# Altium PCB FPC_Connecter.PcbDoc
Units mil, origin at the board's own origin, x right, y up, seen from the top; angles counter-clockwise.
Board outline 1740 x 1360 mil, 2 copper layers (Top Layer, Bottom Layer); 2 components, 33 nets, 80 pads, 28 vias.
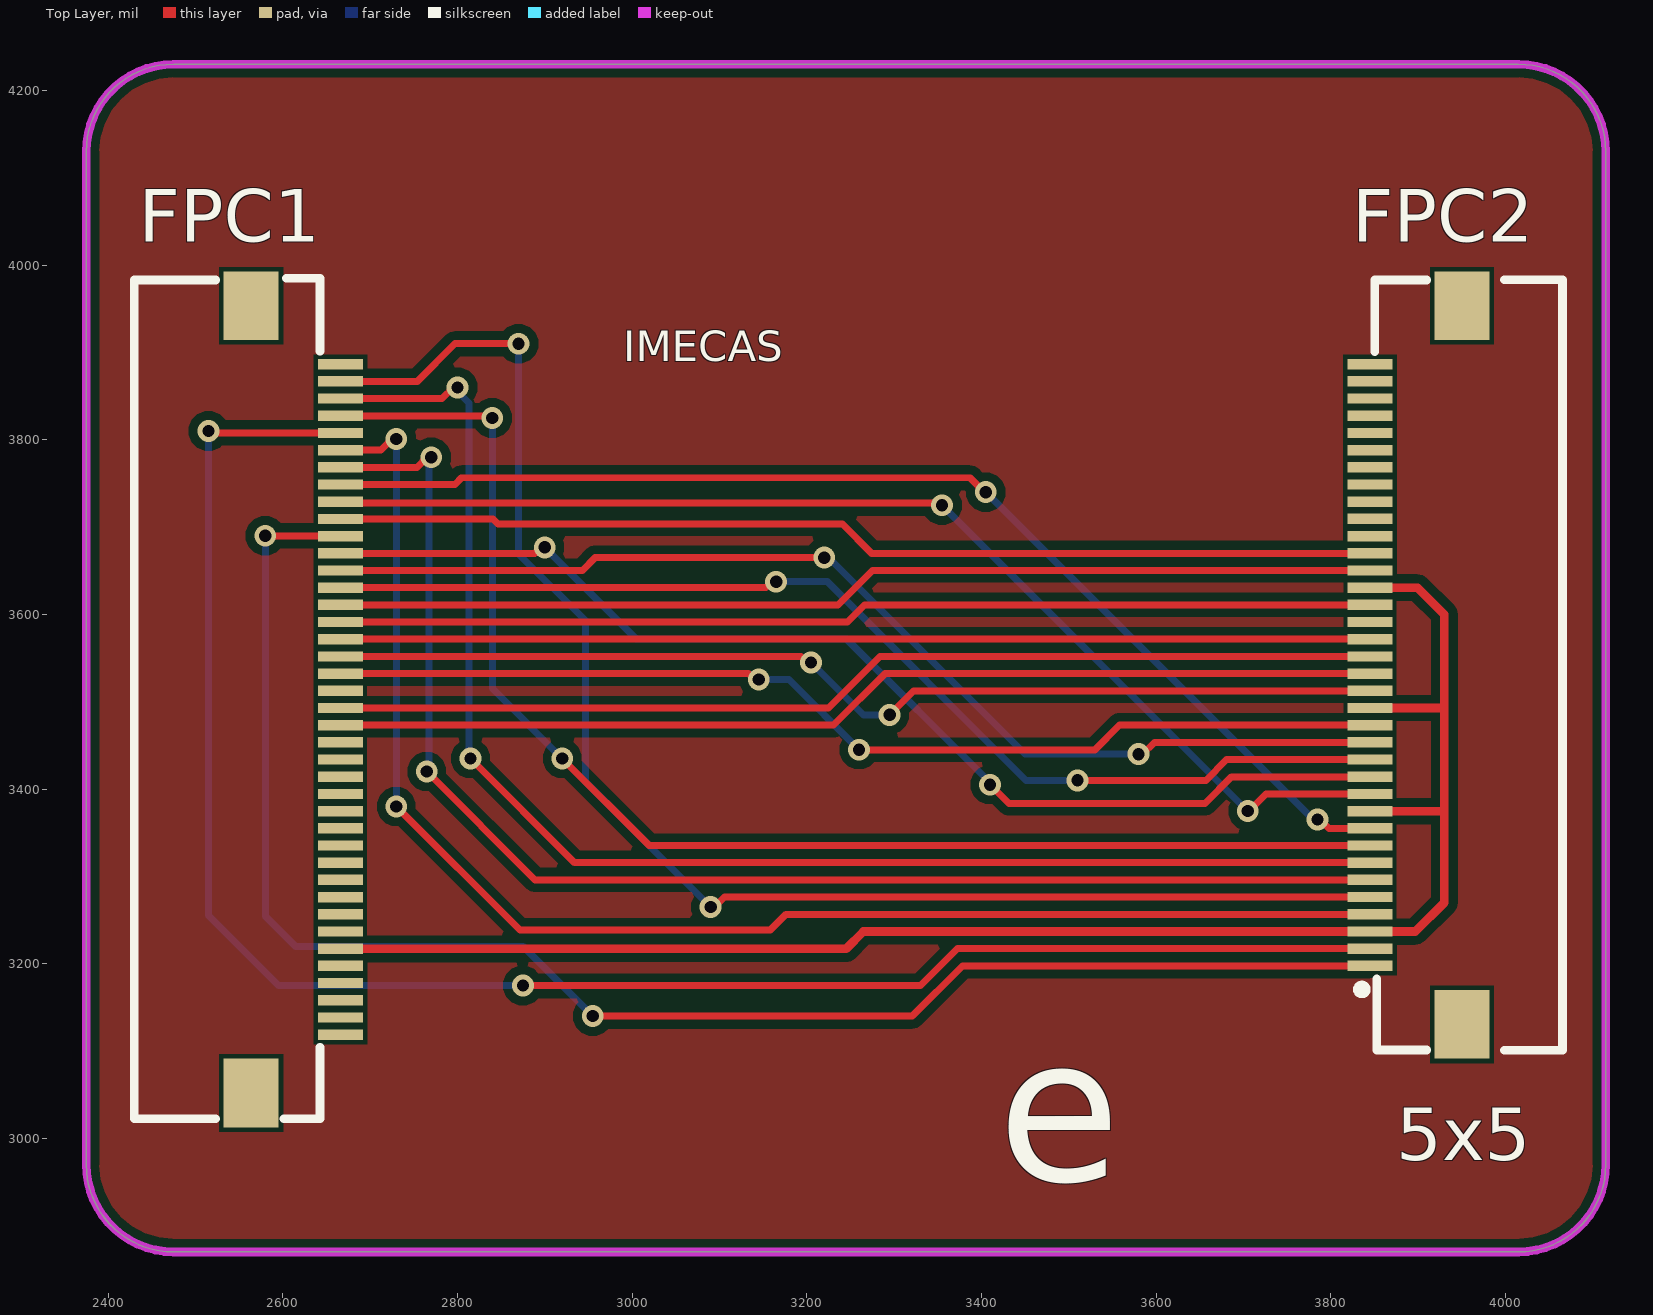
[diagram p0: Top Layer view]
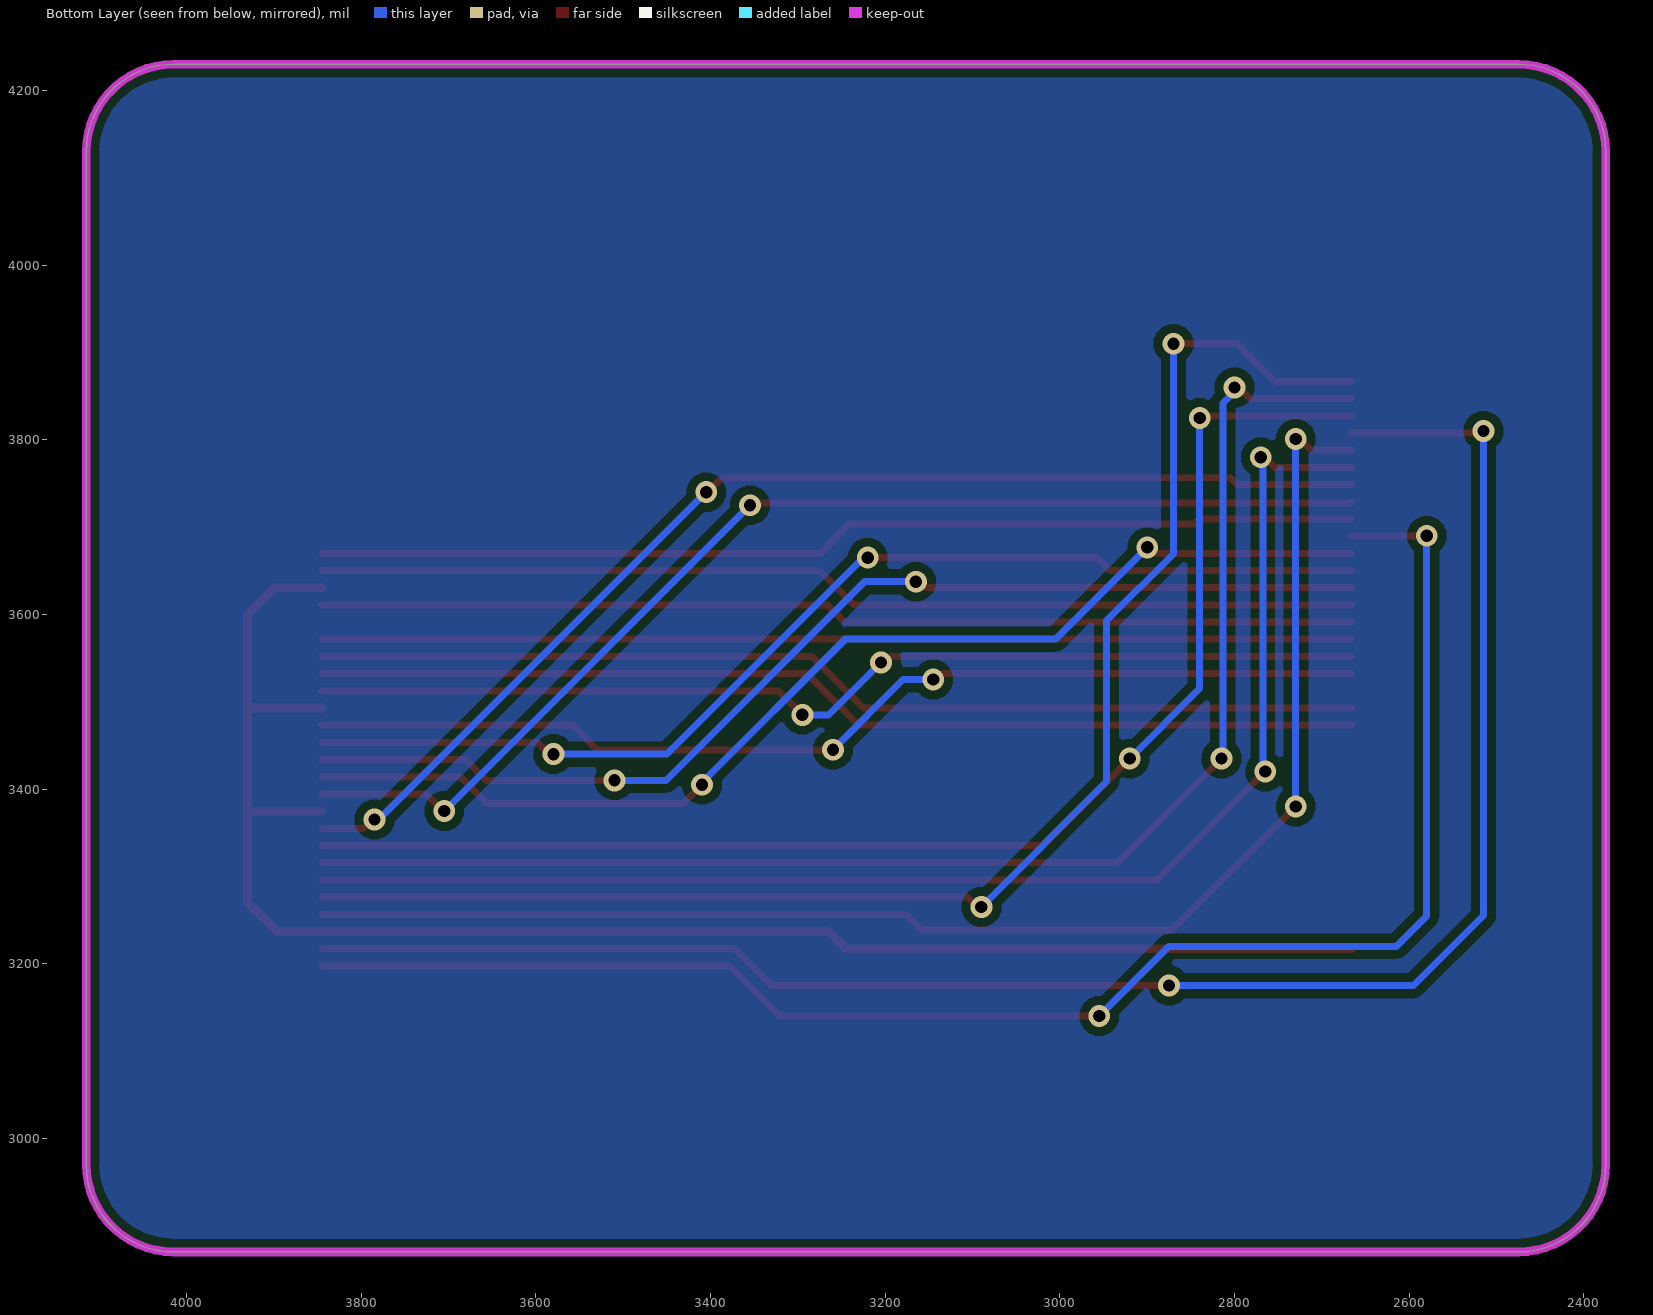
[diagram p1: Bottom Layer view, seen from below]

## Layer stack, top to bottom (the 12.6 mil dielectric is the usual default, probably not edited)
Top Solder: solder mask 0.4, Solder Resist, Dk 3.5
Top Layer: signal copper 1.4
Dielectric 1: dielectric 12.6, FR-4, Dk 4.8
Bottom Layer: signal copper 1.4
Bottom Solder: solder mask 0.4, Solder Resist, Dk 3.5

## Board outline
2375,2970 2375,4130 cw(c2475,4130) 2475,4230 4015,4230 cw(c4015,4130) 4115,4130 4115,2970 cw(c4015,2970) 4015,2870 2475,2870 cw(c2475,2970)

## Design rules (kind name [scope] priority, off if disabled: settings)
Clearance Clearance_2 [(InComponent('FPC1') OR InComponent('FPC2'))] p1: gap=5 ignorepadtopadclearanceinfootprint=FALSE
Clearance [All] p2: gap=10 ignorepadtopadclearanceinfootprint=FALSE except(0: Arc-Hole Track-Hole SMDPad-Hole THPad-Hole Via-Hole Fill-Hole Poly-Hole Region-Hole Text-Hole)
PolygonConnect [All] p1: connectstyle=Relief reliefconductorwidth=10 reliefentries=4 polygonreliefangle="90 Angle" airgapwidth=10
RoutingVias [All] p1: holewidth=14 width=25 viastyle="Through Hole" minholewidth=14 minwidth=25 maxholewidth=14 maxwidth=25
SolderMaskExpansion [All] p1: expansion=4 istentingtop=FALSE
Width [All] p1: maxlimit=10 minlimit=8 preferedwidth=8 minimp=50.000000 maximp=50.000000 favimp=50.000000
30 further rules are at their usual default settings.

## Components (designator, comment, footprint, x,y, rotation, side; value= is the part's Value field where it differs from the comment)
FPC1 "AFC01-S40FCA-00" FPC-SMD_P0.50-40P_FGS-XJ-H2.0 2615,3502.67 r90 top
FPC2 "AFC01-S36FCA-00" FPC-SMD_AFC01-S36FCA-00 3897.76,3542.05 r90 top

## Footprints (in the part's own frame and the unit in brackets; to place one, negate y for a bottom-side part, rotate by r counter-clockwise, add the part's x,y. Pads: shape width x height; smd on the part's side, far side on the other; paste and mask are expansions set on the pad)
FPC-SMD_AFC01-S36FCA-00 [mm]
  rect 0.3x1.3 smd: 1(-8.75,1.34) 2(-8.25,1.339) 3(-7.75,1.34) 4(-7.25,1.34) 5(-6.75,1.34) 6(-6.25,1.34) 7(-5.75,1.34) 8(-5.25,1.34) 9(-4.75,1.34) 10(-4.25,1.34) 11(-3.75,1.34) 12(-3.25,1.34) 13(-2.75,1.34) 14(-2.25,1.34) 15(-1.75,1.34) 16(-1.25,1.34) 17(-0.75,1.34) 18(-0.25,1.34) 19(0.25,1.34) 20(0.75,1.34) 21(1.25,1.34) 22(1.75,1.34) 23(2.25,1.34) 24(2.75,1.34) 25(3.25,1.34) 26(3.75,1.34) 27(4.25,1.34) 28(4.75,1.34) 29(5.25,1.34) 30(5.75,1.34) 31(6.25,1.34) 32(6.75,1.34) 33(7.25,1.34) 34(7.75,1.34) 35(8.25,1.34) 36(8.75,1.34)
  rect 2x1.6 smd: 37(10.45,-1.34) 38(-10.45,-1.34)
  silkscreen extent -11.21,-4.26 11.21,1.7
FPC-SMD_P0.50-40P_FGS-XJ-H2.0 [mm]
  rect 0.3x1.3 smd paste+0 mask+0.05: 1(9.75,-1.3) 2(9.25,-1.3) 3(8.75,-1.3) 4(8.25,-1.3) 5(7.75,-1.3) 6(7.25,-1.3) 7(6.75,-1.3) 8(6.25,-1.3) 9(5.75,-1.3) 10(5.25,-1.3) 11(4.75,-1.3) 12(4.25,-1.3) 13(3.75,-1.3) 14(3.25,-1.3) 15(2.75,-1.3) 16(2.25,-1.3) 17(1.75,-1.3) 18(1.25,-1.3) 19(0.75,-1.3) 20(0.25,-1.3) 21(-0.25,-1.3) 22(-0.75,-1.3) 23(-1.25,-1.3) 24(-1.75,-1.3) 25(-2.25,-1.3) 26(-2.75,-1.3) 27(-3.25,-1.3) 28(-3.75,-1.3) 29(-4.25,-1.3) 30(-4.75,-1.3) 31(-5.25,-1.3) 32(-5.75,-1.3) 33(-6.25,-1.3) 34(-6.75,-1.3) 35(-7.25,-1.3) 36(-7.75,-1.3) 37(-8.25,-1.3) 38(-8.75,-1.3) 39(-9.25,-1.3) 40(-9.75,-1.3)
  rect 2x1.6 smd: 41(-11.45,1.3) 42(11.45,1.3)
  silkscreen extent -12.2,-0.7 12.25,4.7

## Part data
FPC1: JLCPCB Part Class="Extended Part", LCSC Part Name="间距:0.5mm P数:40P 翻盖式 下接", Manufacturer=JS(钜硕电子)
FPC2: JLCPCB Part Class="Extended Part", LCSC Part Name="间距:0.5mm P数:36P 翻盖式 下接", Manufacturer=JS(钜硕电子), Operating Temperature Range=-

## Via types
v1: diameter 25, hole 14, Top Layer to Bottom Layer, 28 vias

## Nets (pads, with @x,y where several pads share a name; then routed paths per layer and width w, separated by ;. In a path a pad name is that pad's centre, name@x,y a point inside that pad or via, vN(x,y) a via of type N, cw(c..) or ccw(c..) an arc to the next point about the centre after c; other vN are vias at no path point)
NetFPC1_2: FPC1.2 FPC2.5 | length 1717.5
  Top Layer w8: FPC1.2 2754.05,3866.84 2797.21,3910 v1(2870,3910) ; v1(3090,3265) 3094.6,3265 3105.9,3276.3 FPC2.5
  Bottom Layer w8: v1(2870,3910) 2870,3669.33 2946.5,3592.83 2946.5,3408.5 v1(3090,3265)
NetFPC1_3: FPC1.3 FPC2.7 | length 1649.8
  Top Layer w8: FPC1.3 2782.56,3847.16 2795.4,3860 v1(2800,3860) ; v1(2815,3435) 2934.33,3315.67 FPC2.7
  Bottom Layer w8: v1(2800,3860) 2800,3855.4 2813.5,3841.9 2813.5,3436.5 v1(2815,3435)
NetFPC1_4: FPC1.4 FPC2.8 | length 1564.3
  Top Layer w8: FPC1.4 2837.53,3827.47 v1(2840,3825) ; v1(2920,3435) 3019.65,3335.35 FPC2.8
  Bottom Layer w8: v1(2840,3825) 2840,3515 v1(2920,3435)
NetFPC1_5: FPC1.5 FPC2.2 | length 2087.8
  Top Layer w8: v1(2515,3810) 2517.21,3807.79 FPC1.5 ; v1(2875,3175) 3330.41,3175 3372.65,3217.24 FPC2.2
  Bottom Layer w8: v1(2515,3810) 2515,3255 2595,3175 v1(2875,3175)
NetFPC1_6: FPC1.6 FPC2.4 | length 1671.2
  Top Layer w8: FPC1.6 2712.53,3788.1 2725.4,3800.97 v1(2730,3800.97) ; v1(2730,3380) 2871.5,3238.5 3158.3,3238.5 3176.41,3256.61 FPC2.4
  Bottom Layer w8: v1(2730,3380) v1(2730,3800.97)
NetFPC1_7: FPC1.7 FPC2.6 | length 1602.1
  Top Layer w8: FPC1.7 2753.82,3768.42 2765.4,3780 v1(2770,3780) ; v1(2765,3420) 2889.02,3295.98 FPC2.6
  Bottom Layer w8: v1(2765,3420) 2767.5,3422.5 2767.5,3777.5 v1(2770,3780)
NetFPC1_8: FPC1.8 FPC2.9 | length 1348.3
  Top Layer w8: FPC1.8 2797.04,3748.73 2804.81,3756.5 3386.85,3756.5 3403.35,3740 v1(3405,3740) ; v1(3785,3365) 3788.23,3365 3798.19,3355.04 FPC2.9
  Bottom Layer w8: v1(3405,3740) 3773.84,3371.16 3774.24,3371.16 3780.4,3365 v1(3785,3365)
NetFPC1_9: FPC1.9 FPC2.11 | length 1333.5
  Top Layer w8: FPC1.9 2667.87,3727.36 3352.64,3727.36 v1(3355,3725) ; v1(3705,3375) 3706.49,3375 3725.9,3394.41 FPC2.11
  Bottom Layer w8: v1(3355,3725) v1(3705,3375)
NetFPC1_10: FPC1.10 FPC2.25 | length 1195.1
  Top Layer w8: FPC1.10 2840.64,3709.36 2846.5,3703.5 3240.82,3703.5 3274.32,3670 FPC2.25
NetFPC1_11: FPC1.11 FPC2.1 | length 1858
  Top Layer w8: v1(2580,3690) 2580.16,3689.84 2666.02,3689.84 FPC1.11 ; v1(2955,3140) 3320.87,3140 3378.43,3197.56 FPC2.1
  Bottom Layer w8: v1(2580,3690) 2580,3254.69 2614.69,3220 2875,3220 v1(2955,3140)
NetFPC1_12: FPC1.12 FPC2.12 | length 1317.3
  Top Layer w8: FPC1.12 2888.58,3669.99 2895.4,3676.81 v1(2900,3676.81) ; v1(3410,3405) 3431.5,3383.5 3656.07,3383.5 3686.66,3414.09 FPC2.12
  Bottom Layer w8: v1(2900,3676.81) 3005.24,3571.57 3245.91,3571.57 3410,3407.48 v1(3410,3405)
NetFPC1_13: FPC1.13 FPC2.14 | length 1283.7
  Top Layer w8: FPC1.13 2943.14,3650.31 2957.83,3665 v1(3220,3665) ; v1(3580,3440) 3584.6,3440 3598.06,3453.46 FPC2.14
  Bottom Layer w8: v1(3220,3665) 3225,3665 3450,3440 v1(3580,3440)
NetFPC1_14: FPC1.14 FPC2.13 | length 1285.7
  Top Layer w8: FPC1.14 3153.58,3630.62 3160.4,3637.44 v1(3165,3637.44) ; v1(3510,3410) 3657.11,3410 3680.89,3433.78 FPC2.13
  Bottom Layer w8: v1(3165,3637.44) 3223.78,3637.44 3451.22,3410 v1(3510,3410)
NetFPC1_15: FPC1.15 FPC2.24 | length 1195.1
  Top Layer w8: FPC1.15 3235.91,3610.94 3275.28,3650.31 FPC2.24
NetFPC1_16: FPC1.16 FPC2.22 | length 1187
  Top Layer w8: FPC1.16 3246.7,3591.25 3266.39,3610.94 FPC2.22
NetFPC1_17: FPC1.17 FPC2.20 | length 1178.8
  Top Layer w8: FPC1.17 FPC2.20
NetFPC1_18: FPC1.18 FPC2.17 | length 1217.9
  Top Layer w8: FPC1.18 3193.59,3551.88 3200.4,3545.07 v1(3205,3545.07) ; v1(3295,3485) 3322.52,3512.52 FPC2.17
  Bottom Layer w8: v1(3205,3545.07) 3265.07,3485 v1(3295,3485)
NetFPC1_19: FPC1.19 FPC2.15 | length 1226.6
  Top Layer w8: FPC1.19 3133.58,3532.2 3140.4,3525.38 v1(3145,3525.38) ; v1(3260,3445) 3529.93,3445 3558.08,3473.15 FPC2.15
  Bottom Layer w8: v1(3145,3525.38) 3179.62,3525.38 v1(3260,3445)
NetFPC1_20: FPC1.20
NetFPC1_21: FPC1.21 FPC2.19 | length 1203.3
  Top Layer w8: FPC1.21 3225.11,3492.83 3284.17,3551.89 FPC2.19
NetFPC1_22: FPC1.22 FPC2.18 | length 1203.3
  Top Layer w8: FPC1.22 3230.87,3473.14 3289.93,3532.2 FPC2.18
NetFPC1_23: FPC1.23
NetFPC1_24: FPC1.24
NetFPC1_25: FPC1.25
NetFPC1_26: FPC1.26
NetFPC1_27: FPC1.27
NetFPC1_28: FPC1.28
NetFPC1_29: FPC1.29
NetFPC1_30: FPC1.30
NetFPC1_31: FPC1.31
NetFPC1_32: FPC1.32
NetFPC1_33: FPC1.33
NetFPC1_35: FPC1.35 FPC2.3 FPC2.10 FPC2.16 FPC2.23 | length 1884.4
  Top Layer w10: FPC1.35 3245.29,3217.24 3264.98,3236.93 3896.93,3236.93 3930,3270 3930,3375 ; FPC2.10 3929.72,3374.72 3930,3375 ; FPC2.16 3927.83,3492.83 3930,3495 ; FPC2.23 3899.37,3630.63 3930,3600 3930,3495 ; 3930,3375 3930,3495
pads on no net: FPC1.1 FPC1.34 FPC1.36 FPC1.37 FPC1.38 FPC1.39 FPC1.40 FPC1.41 FPC1.42 FPC2.21 FPC2.26 FPC2.27 FPC2.28 FPC2.29 FPC2.30 FPC2.31 FPC2.32 FPC2.33 FPC2.34 FPC2.35 FPC2.36 FPC2.37 FPC2.38

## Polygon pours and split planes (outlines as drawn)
no net on Top Layer "NONET_L01_P002" (solid, pour order 2): 2375,2970 2375,4130 cw(c2475,4130) 2475,4230 4015,4230 cw(c4015,4130) 4115,4130 4115,2970 cw(c4015,2970) 4015,2870 2475,2870 cw(c2475,2970)
no net on Bottom Layer "NONET_L02_P003" (solid, pour order 3): 2375,2970 2375,4130 cw(c2475,4130) 2475,4230 4015,4230 cw(c4015,4130) 4115,4130 4115,2970 cw(c4015,2970) 4015,2870 2475,2870 cw(c2475,2970)

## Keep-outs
Keep-Out Layer:
  the board outline again, w10

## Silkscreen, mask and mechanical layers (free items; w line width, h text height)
Top Overlay:
  text "IMECAS" at 2990,3890 h35
  text "5x5" at 3875,2975 h60
  text "e" at 3418.96,2893.97 h300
